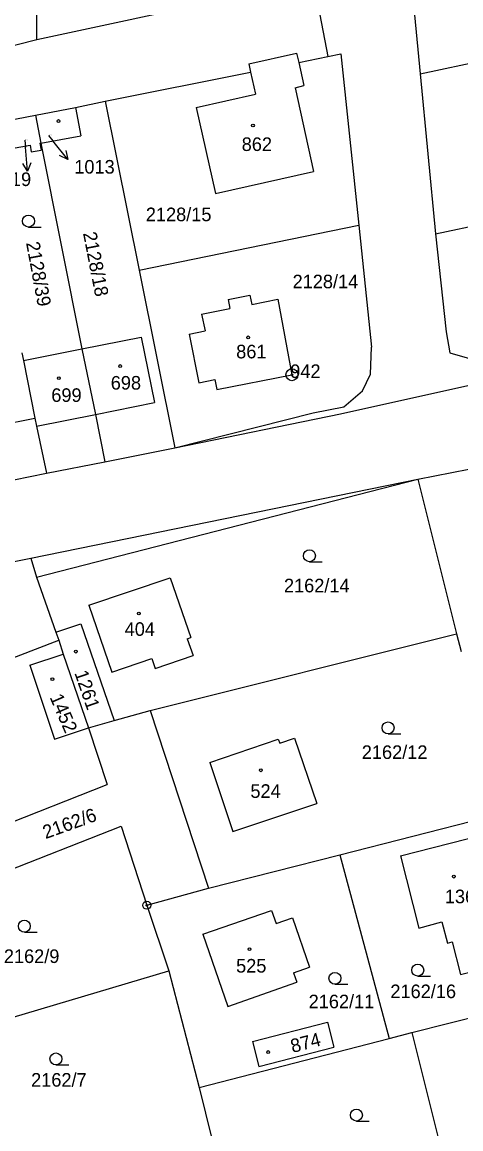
# Model space of a CAD drawing. Extents: x -763205 to -760228, y -1155311 to -1152844.
# Drawn here: x -762365.1 to -762310.2, y -1154772.5 to -1154633.9 of the extents above; entities that cross this region are included whole.
import ezdxf

# ---------------------------------------------------------------- set-up
doc = ezdxf.new("R2010")
doc.units = 0
for name, color, linetype in [('Vrstva 1', 7, 'Continuous'), ('Vrstva 16', 7, 'Continuous'), ('Vrstva 17', 7, 'Continuous'), ('Vrstva 18', 7, 'Continuous'), ('Vrstva 19', 7, 'Continuous'), ('Vrstva 24', 7, 'Continuous'), ('Vrstva 25', 7, 'Continuous'), ('Vrstva 4', 7, 'Continuous')]:
    doc.layers.add(name, color=color, linetype=linetype)

msp = doc.modelspace()

# ---------------------------------------------------------------- linework, layer by layer
at = {"layer": 'Vrstva 1'}
for p, q in [((-762363.25, -1154636.12), (-762363.23, -1154579.28)), ((-762316.51, -1154627.43), (-762315.27, -1154640.42)), ((-762363.25, -1154636.12), (-762328.69, -1154628.63)), ((-762328.69, -1154628.63), (-762326.83, -1154638.25)), ((-762315.27, -1154640.42), (-762286.15, -1154634.23)), ((-762435.88, -1154654.73), (-762363.25, -1154636.12)), ((-762336.74, -1154639.17), (-762330.75, -1154637.84)), ((-762330.75, -1154637.84), (-762330.48, -1154638.99)), ((-762330.48, -1154638.99), (-762326.83, -1154638.25)), ((-762326.83, -1154638.25), (-762325.21, -1154637.92)), ((-762325.21, -1154637.92), (-762322.95, -1154659.38)), ((-762354.71, -1154643.85), (-762336.51, -1154640.2)), ((-762336.74, -1154639.17), (-762336.51, -1154640.2)), ((-762336.51, -1154640.2), (-762335.9, -1154642.98)), ((-762330.48, -1154638.99), (-762329.82, -1154641.87)), ((-762315.27, -1154640.42), (-762313.37, -1154660.46)), ((-762343.33, -1154644.62), (-762335.9, -1154642.98)), ((-762330.9, -1154642.18), (-762329.82, -1154641.87)), ((-762330.9, -1154642.18), (-762328.63, -1154652.64)), ((-762358.43, -1154644.65), (-762354.71, -1154643.85)), ((-762354.71, -1154643.85), (-762350.45, -1154665.01)), ((-762368.75, -1154646.6), (-762363.41, -1154645.59)), ((-762363.41, -1154645.59), (-762358.43, -1154644.65)), ((-762363.41, -1154645.59), (-762362.76, -1154649.1)), ((-762358.43, -1154644.65), (-762357.76, -1154648.18)), ((-762343.33, -1154644.62), (-762340.91, -1154655.39)), ((-762362.76, -1154649.1), (-762357.76, -1154648.18)), ((-762368.09, -1154650.08), (-762364.11, -1154649.35)), ((-762364.11, -1154649.35), (-762363.96, -1154650.19)), ((-762363.96, -1154650.19), (-762362.7, -1154649.96)), ((-762362.86, -1154649.12), (-762362.76, -1154649.1)), ((-762362.86, -1154649.12), (-762362.7, -1154649.96)), ((-762362.76, -1154649.1), (-762357.62, -1154674.85)), ((-762340.91, -1154655.39), (-762328.63, -1154652.64)), ((-762313.37, -1154660.46), (-762281.43, -1154653.63)), ((-762350.45, -1154665.01), (-762322.95, -1154659.38)), ((-762322.95, -1154659.38), (-762321.35, -1154674.64)), ((-762313.37, -1154660.46), (-762312.04, -1154672.7)), ((-762350.45, -1154665.01), (-762345.98, -1154687.24)), ((-762339.32, -1154668.67), (-762336.59, -1154668.13)), ((-762339.32, -1154668.67), (-762339.09, -1154669.8)), ((-762336.59, -1154668.13), (-762336.36, -1154669.29)), ((-762336.36, -1154669.29), (-762333.1, -1154668.61)), ((-762333.1, -1154668.61), (-762331.32, -1154678.09)), ((-762342.63, -1154670.5), (-762339.09, -1154669.8)), ((-762342.63, -1154670.5), (-762342.2, -1154672.61)), ((-762357.62, -1154674.85), (-762350.19, -1154673.37)), ((-762350.19, -1154673.37), (-762348.53, -1154681.58)), ((-762344.2, -1154673.01), (-762342.2, -1154672.61)), ((-762344.2, -1154673.01), (-762342.98, -1154679.1)), ((-762312.04, -1154672.7), (-762311.56, -1154675.35)), ((-762364.94, -1154676.31), (-762357.62, -1154674.85)), ((-762357.62, -1154674.85), (-762355.92, -1154683.06)), ((-762321.49, -1154678.02), (-762321.35, -1154674.64)), ((-762365.14, -1154675.36), (-762364.94, -1154676.31)), ((-762364.94, -1154676.31), (-762363.49, -1154683.52)), ((-762311.56, -1154675.35), (-762302.5, -1154677.93)), ((-762342.98, -1154679.1), (-762340.98, -1154678.7)), ((-762340.98, -1154678.7), (-762340.73, -1154679.95)), ((-762340.73, -1154679.95), (-762331.32, -1154678.09)), ((-762325.26, -1154683), (-762302.5, -1154677.93)), ((-762322.51, -1154680.12), (-762321.49, -1154678.02)), ((-762324.84, -1154682.09), (-762322.51, -1154680.12)), ((-762355.92, -1154683.06), (-762348.53, -1154681.58)), ((-762355.92, -1154683.06), (-762354.76, -1154688.99)), ((-762345.98, -1154687.24), (-762328.66, -1154682.85)), ((-762345.98, -1154687.24), (-762325.26, -1154683)), ((-762328.66, -1154682.85), (-762324.84, -1154682.09)), ((-762363.49, -1154683.52), (-762363.29, -1154684.53)), ((-762363.29, -1154684.53), (-762362.05, -1154690.41)), ((-762315.58, -1154691.17), (-762276.24, -1154683.45)), ((-762354.76, -1154688.99), (-762345.98, -1154687.24)), ((-762362.05, -1154690.41), (-762354.76, -1154688.99)), ((-762369.32, -1154691.88), (-762362.05, -1154690.41)), ((-762363.3, -1154703.42), (-762315.58, -1154691.17)), ((-762315.58, -1154691.17), (-762310.72, -1154710.51)), ((-762387.95, -1154705.9), (-762364.01, -1154701.06)), ((-762364.01, -1154701.06), (-762363.3, -1154703.42)), ((-762363.3, -1154703.42), (-762360.87, -1154710.32)), ((-762356.74, -1154706.95), (-762346.57, -1154703.5)), ((-762346.57, -1154703.5), (-762343.98, -1154711)), ((-762356.74, -1154706.95), (-762353.85, -1154715.31)), ((-762360.87, -1154710.32), (-762357.75, -1154709.26)), ((-762357.75, -1154709.26), (-762353.57, -1154721.39)), ((-762360.87, -1154710.32), (-762360.52, -1154711.32)), ((-762349.07, -1154720.11), (-762310.72, -1154710.51)), ((-762310.72, -1154710.51), (-762310.15, -1154712.75)), ((-762382.93, -1154719.92), (-762360.52, -1154711.32)), ((-762360.52, -1154711.32), (-762359.96, -1154713.06)), ((-762344.43, -1154711.15), (-762343.98, -1154711)), ((-762344.43, -1154711.15), (-762343.7, -1154713.24)), ((-762364.13, -1154714.44), (-762359.96, -1154713.06)), ((-762359.96, -1154713.06), (-762356.79, -1154722.31)), ((-762353.85, -1154715.31), (-762348.88, -1154713.62)), ((-762348.88, -1154713.62), (-762348.45, -1154714.85)), ((-762348.45, -1154714.85), (-762343.7, -1154713.24)), ((-762364.13, -1154714.44), (-762361.04, -1154723.72)), ((-762353.57, -1154721.39), (-762349.07, -1154720.11)), ((-762349.07, -1154720.11), (-762341.77, -1154742.38)), ((-762356.79, -1154722.31), (-762353.57, -1154721.39)), ((-762361.04, -1154723.72), (-762356.79, -1154722.31)), ((-762356.79, -1154722.31), (-762354.47, -1154729.38)), ((-762341.61, -1154726.63), (-762333.03, -1154723.7)), ((-762333.03, -1154723.7), (-762332.85, -1154724.22)), ((-762332.85, -1154724.22), (-762330.99, -1154723.58)), ((-762330.99, -1154723.58), (-762328.22, -1154731.75)), ((-762341.61, -1154726.63), (-762338.74, -1154735.25)), ((-762398.34, -1154746.74), (-762354.47, -1154729.38)), ((-762338.74, -1154735.25), (-762328.22, -1154731.75)), ((-762325.32, -1154738.18), (-762305.03, -1154733)), ((-762396.34, -1154751.8), (-762352.69, -1154734.59)), ((-762352.69, -1154734.59), (-762349.49, -1154744.5)), ((-762317.72, -1154738.33), (-762307.41, -1154735.7)), ((-762341.77, -1154742.38), (-762325.32, -1154738.18)), ((-762325.32, -1154738.18), (-762319.17, -1154761.17)), ((-762317.72, -1154738.33), (-762315.46, -1154747.35)), ((-762349.49, -1154744.5), (-762341.77, -1154742.38)), ((-762349.49, -1154744.5), (-762346.72, -1154752.73)), ((-762342.46, -1154748.13), (-762333.87, -1154745.17)), ((-762333.87, -1154745.17), (-762333.3, -1154746.78)), ((-762333.3, -1154746.78), (-762331.27, -1154746.06)), ((-762331.27, -1154746.06), (-762329.13, -1154752.25)), ((-762315.46, -1154747.35), (-762312.56, -1154746.58)), ((-762312.56, -1154746.58), (-762311.87, -1154749.26)), ((-762342.46, -1154748.13), (-762339.33, -1154757.18)), ((-762311.87, -1154749.26), (-762311.26, -1154749.1)), ((-762311.26, -1154749.1), (-762310.21, -1154753.19)), ((-762331.12, -1154752.95), (-762329.13, -1154752.25)), ((-762310.21, -1154753.19), (-762303.38, -1154751.44)), ((-762390.82, -1154765.82), (-762346.72, -1154752.73)), ((-762346.72, -1154752.73), (-762342.92, -1154767.33)), ((-762331.12, -1154752.95), (-762330.7, -1154754.13)), ((-762339.33, -1154757.18), (-762330.7, -1154754.13)), ((-762316.33, -1154760.43), (-762299.11, -1154756.12)), ((-762336.26, -1154761.55), (-762326.88, -1154759.15)), ((-762326.88, -1154759.15), (-762326.08, -1154762.27)), ((-762319.17, -1154761.17), (-762316.33, -1154760.43)), ((-762316.33, -1154760.43), (-762310.8, -1154782.47)), ((-762342.92, -1154767.33), (-762319.17, -1154761.17)), ((-762336.26, -1154761.55), (-762335.46, -1154764.67)), ((-762335.46, -1154764.67), (-762326.08, -1154762.27)), ((-762342.92, -1154767.33), (-762341.36, -1154773.75))]:
    msp.add_line(p, q, dxfattribs=at)
at = {"layer": 'Vrstva 16'}
for p, q in [((-762361.78, -1154648.14), (-762361.26, -1154648.79)), ((-762364.74, -1154648.74), (-762364.67, -1154649.62)), ((-762364.423, -1154652.61), (-762364.67, -1154649.62)), ((-762359.387, -1154651.133), (-762361.26, -1154648.79))]:
    msp.add_line(p, q, dxfattribs=at)
for points in [[(-762359.621, -1154650.04), (-762359.387, -1154651.133), (-762360.402, -1154650.664)], [(-762364.007, -1154651.572), (-762364.423, -1154652.61), (-762365.004, -1154651.654)]]:
    msp.add_lwpolyline(points, dxfattribs=at)
at = {"layer": 'Vrstva 24'}
for centre, radius in [((-762331.32, -1154678.09), 0.75), ((-762331.32, -1154678.09), 0.1), ((-762349.49, -1154744.5), 0.5), ((-762349.49, -1154744.5), 0.1)]:
    msp.add_circle(centre, radius, dxfattribs=at)
at = {"layer": 'Vrstva 25'}
for p, q in [((-762364.3, -1154659.6), (-762362.7, -1154659.6)), ((-762329.13, -1154701.5), (-762327.53, -1154701.5)), ((-762319.29, -1154723.05), (-762317.69, -1154723.05)), ((-762364.82, -1154747.87), (-762363.22, -1154747.87)), ((-762315.58, -1154753.37), (-762313.98, -1154753.37)), ((-762325.94, -1154754.4), (-762324.34, -1154754.4)), ((-762360.86, -1154764.49), (-762359.26, -1154764.49)), ((-762323.26, -1154771.52), (-762321.66, -1154771.52))]:
    msp.add_line(p, q, dxfattribs=at)
for centre, radius in [((-762360.55, -1154646.33), 0.175), ((-762336.2, -1154646.89), 0.175), ((-762364.3, -1154658.85), 0.75), ((-762336.81, -1154673.41), 0.175), ((-762352.83, -1154677), 0.175), ((-762360.5, -1154678.53), 0.175), ((-762329.13, -1154700.75), 0.75), ((-762350.48, -1154707.98), 0.175), ((-762358.38, -1154712.75), 0.175), ((-762361.31, -1154716.19), 0.175), ((-762319.29, -1154722.3), 0.75), ((-762335.23, -1154727.61), 0.175), ((-762311.05, -1154740.92), 0.175), ((-762364.82, -1154747.12), 0.75), ((-762336.64, -1154749.99), 0.175), ((-762315.58, -1154752.62), 0.75), ((-762325.94, -1154753.65), 0.75), ((-762360.86, -1154763.74), 0.75), ((-762334.31, -1154762.88), 0.175), ((-762323.26, -1154770.77), 0.75)]:
    msp.add_circle(centre, radius, dxfattribs=at)
at = {"layer": 'Vrstva 4'}
for p, q in [((-762363.29, -1154684.53), (-762355.92, -1154683.06)), ((-762370.83, -1154684.99), (-762363.49, -1154683.52)), ((-762364.01, -1154701.06), (-762315.58, -1154691.17))]:
    msp.add_line(p, q, dxfattribs=at)

# ---------------------------------------------------------------- texts
at = {"layer": 'Vrstva 16'}
for s, p in [('1013', (-762358.567, -1154652.91)), ('1019', (-762369.026, -1154654.47))]:
    msp.add_text(s, height=1.7, dxfattribs=at).set_placement(p)
at = {"layer": 'Vrstva 17'}
msp.add_text('942', height=1.7, dxfattribs=at).set_placement((-762331.534, -1154678.5))
at = {"layer": 'Vrstva 18'}
for s, p in [('2128/15', (-762349.613, -1154658.87)), ('2128/14', (-762331.243, -1154667.27)), ('2162/14', (-762332.323, -1154705.33)), ('2162/12', (-762322.583, -1154726.19)), ('2162/9', (-762367.383, -1154751.73)), ('2162/16', (-762319.003, -1154756.13)), ('2162/11', (-762329.233, -1154757.4)), ('2162/7', (-762363.973, -1154767.21))]:
    msp.add_text(s, height=1.7, dxfattribs=at).set_placement(p)
for s, rotation, p in [('2128/18', 281.0358, (-762357.485, -1154660.363)), ('2128/39', 280.57743, (-762364.616, -1154661.583)), ('2162/6', 19.76704, (-762362.157, -1154736.23))]:
    msp.add_text(s, height=1.7, rotation=rotation, dxfattribs=at).set_placement(p)
at = {"layer": 'Vrstva 19'}
for s, height, p in [('1013', 0.1, (-762361.757, -1154648.14)), ('862', 1.7, (-762337.613, -1154650.08)), ('1019', 0.1, (-762364.717, -1154648.74)), ('861', 1.7, (-762338.303, -1154676.04)), ('698', 1.7, (-762354.003, -1154679.95)), ('699', 1.7, (-762361.443, -1154681.49)), ('404', 1.7, (-762352.263, -1154710.78)), ('524', 1.7, (-762336.523, -1154731.06)), ('1360', 1.7, (-762312.187, -1154744.25)), ('525', 1.7, (-762338.313, -1154752.93))]:
    msp.add_text(s, height=height, dxfattribs=at).set_placement(p)
for s, rotation, p in [('1261', 288.99991, (-762358.572, -1154715.411)), ('1452', 293.29709, (-762361.675, -1154718.461)), ('874', 14.61043, (-762331.25, -1154763))]:
    msp.add_text(s, height=1.7, rotation=rotation, dxfattribs=at).set_placement(p)

doc.saveas('drawing.dxf')
